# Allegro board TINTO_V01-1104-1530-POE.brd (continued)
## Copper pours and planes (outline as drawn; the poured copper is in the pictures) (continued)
GEN_3V3 on BOTTOM (solid shape): 139.4,153.53 139.4,152.48 140.57,151.32 140.57,149.41 140.32,149.16 139,149.16 138.84,149.31 138.84,150.66 138.01,151.49 134.91,151.49 134.86,151.54 134.86,153.51 134.96,153.61 139.32,153.61
GEN_3V3 on BOTTOM (solid shape): 136.18,167.14 136.18,164.35 136,164.17 132.75,164.17 132.74,164.17 132.6,164.19 132.45,164.17 132.44,164.17 131.96,164.17 131.66,164.47 131.66,167.05 131.91,167.31 132.76,167.31 132.77,167.32 136,167.32
GEN_3V3 on BOTTOM (solid shape): 144.38,82.79 144.38,77.71 141.21,74.53 134.6,74.53 134.22,74.15 134.22,50.28 131.43,47.48 108.7,47.48 107.16,45.94 107.16,31.46 106.91,31.22 106.09,31.22 105.88,31.42 105.88,47.21 107.93,49.26 130.79,49.26 132.44,50.91 132.44,75.04 133.21,75.8 140.95,75.8 142.99,77.83 142.99,80.63 142.81,80.8 141.92,80.8 141.92,80.81 138.24,80.81 137.37,79.94 137.37,78.67 137.3,78.6 136.69,78.6 136.64,78.65 136.64,80.12 135.95,80.81 131.84,80.81 131.76,80.88 131.76,83.22 131.99,83.45 143.72,83.45
GEN_3V3 on BOTTOM (solid shape): 102.86,145.02 102.86,144.79 102.53,144.46 102.53,144.05 102.63,143.79 102.88,143.69 102.91,143.69 102.96,143.65 102.96,143.44 102.85,143.34 102.7,143.34 102.55,143.19 102.55,142.99 102.45,142.88 102.38,142.89 102.27,142.88 102.22,142.94 102.22,143.16 102.45,143.56 102.2,143.94 102.16,143.95 102.16,144.02 102.11,144.21 101.95,144.32 101.89,144.33 101.82,144.32 101.71,144.34 101.66,144.44 101.66,144.64 101.7,144.68 102.14,144.68 102.16,144.69 102.61,145.14 102.73,145.14
GEN_3V3 on BOTTOM (solid shape): outline of 125 points within 100.26,147.39 102.21,149.95
GEN_3V3 on VCC1 (solid shape): outline of 233 points within 10.51,29.7 172.96,192.29
GEN_3V3_IN on BOTTOM (solid shape): 126.12,160.82 126.12,160.55 125.96,160.39 125.96,159.92 125.96,159.88 125.97,159.84 125.97,159.57 126.2,159.34 126.72,159.34 126.81,159.3 126.85,159.21 127.19,158.73 127.72,158.98 127.81,159.05 127.92,159.01 127.95,158.99 127.95,158.22 127.74,158.02 127.16,158.02 126.75,158.43 125.51,158.43 125.13,158.81 125.13,160.21 125.84,160.92 126.02,160.92
GEN_3V3_PMIC on BOTTOM (solid shape): 130.77,166 130.77,164.37 130.59,164.19 130.02,164.19 129.95,164.12 129.78,164.12 129.55,163.89 129.55,163.36 129.22,163.03 125.43,163.03 125.28,163.18 125.28,165.41 125.43,165.57 128.94,165.57 129.35,165.97 129.37,165.97 129.53,165.99 129.67,166.06 129.68,166.07 129.78,166.07 130.69,166.07
GEN_3V3_SW on BOTTOM (solid shape): 127.57,162.44 127.57,162.3 127.56,162.29 127.56,161.82 127.28,161.54 126.68,161.54 126.38,161.25 125.89,161.25 125.76,161.12 125.76,161.12 125.7,161.07 125.69,161.06 125.59,160.99 125.51,160.88 125.51,160.88 124.92,160.29 124.92,159.49 124.87,159.44 124.72,159.44 124.62,159.55 124.62,160.89 125.23,161.5 125.23,162.31 125.43,162.52 127.49,162.52
GLH on TOP (solid shape): 77.33,106.54 87.23,106.54 88.63,107.93 90.15,107.93 92.36,105.73 92.36,102.61 92.1,102.35 89.52,102.35 87.36,104.5 76.95,104.5 76.18,105.27 72.37,105.27 71.99,105.65 71.99,107.81 72.5,108.31 75.55,108.31
GLH on BOTTOM (solid shape): 77.33,106.54 87.23,106.54 88.63,107.93 90.15,107.93 92.36,105.73 92.36,102.61 92.1,102.35 89.52,102.35 87.36,104.5 76.95,104.5 76.18,105.27 72.37,105.27 71.99,105.65 71.99,107.81 72.5,108.31 75.55,108.31
LAN_AVDDL on BOTTOM (solid shape): 108.57,120.51 108.57,120.32 108.31,120.06 107.52,120.06 107.4,119.94 107.2,119.94 107.01,120.12 107.01,120.35 107.3,120.63 108.44,120.63
LAN_DVDD_SW on BOTTOM (solid shape): 105.44,116.56 105.64,116.56 105.82,116.41 105.97,116.36 106.02,116.36 106.08,116.36 106.49,116.36 106.49,116.36 106.54,116.32 106.54,113.9 106.41,113.78 105.39,113.78 105.22,113.95 105.22,115.78 104.89,116.11 104.89,116.78 104.89,116.87 104.91,116.9 105.1,116.9
LCD_AVDD on BOTTOM (solid shape): 125.61,76.72 125.61,75.19 124.98,74.56 122.69,74.56 122.44,74.81 122.44,75.06 122.82,75.45 122.82,77.1 125.23,77.1
LCD_BL+ on BOTTOM (solid shape): 119.24,67.17 119.24,65.39 118.47,64.63 117.05,64.63 116.34,63.92 115.99,63.92 115.91,63.99 115.91,64.98 115.88,65.01 115.73,65.01 115.71,64.98 115.71,63.97 115.66,63.92 115.45,63.92 115.4,63.97 115.4,65.13 115.17,65.36 115.17,67.17 115.3,67.29 119.11,67.29
LCD_BL- on BOTTOM (solid shape): 112.2,64.93 112.2,63.31 112.07,63.18 111.46,63.18 111.39,63.26 111.39,64.93 111.46,65.01 112.12,65.01
LCD_SUP on BOTTOM (solid shape): 122.34,80.24 122.34,75.89 122.03,75.58 119.63,75.58 119.39,75.81 119.39,77.64 119.24,77.79 117.86,77.79 117.61,78.05 117.61,80.53 117.43,80.7 115.96,80.7 115.95,80.7 115.8,80.73 115.65,80.7 115.64,80.7 115.55,80.7 114.78,79.93 113.72,79.93 113.62,80.03 113.62,80.31 113.74,80.42 114.6,80.42 114.71,80.53 114.71,80.53 114.79,80.59 114.85,80.67 114.85,80.67 115.56,81.38 121.19,81.38
LCD_VDD on BOTTOM (solid shape): 96.41,66.74 97.37,66.74 97.73,66.38 97.73,66.25 97.72,66.24 97.65,66.01 97.73,65.79 97.73,63.94 97.64,63.85 96.97,63.85 96.87,63.95 96.87,64.31 96.88,64.32 96.91,64.46 96.88,64.6 96.87,64.61 96.87,65.18 96.14,65.91 92.66,65.91 92.52,66.05 92.52,67.06 92.59,67.13 96.02,67.13
LED_G_POWER_L on BOTTOM (solid shape): 51.19,184.1 51.19,176.04 51.04,175.88 46.97,175.88 46.65,176.21 46.65,182.41 47.49,183.24 47.49,183.97 47.84,184.33 50.97,184.33
LED_R_POWER_L on BOTTOM (solid shape): 68.44,184.01 68.44,182.61 69.25,181.79 69.25,175.94 69.2,175.89 65.02,175.89 64.98,175.93 64.98,179.82 64.75,180.04 64.75,182.36 65.45,183.05 65.45,183.94 65.64,184.13 68.31,184.13
LVDS_2V5 on VCC2 (solid shape): 140.06,155.45 140.06,151.49 140.08,151.4 140.14,151.31 140.95,150.5 140.95,147.41 133.15,139.61 133.1,139.53 133.08,139.43 133.1,139.34 133.14,139.26 133.14,137.98 132.44,137.28 132.4,137.22 132.38,137.14 132.38,135.57 132.24,135.43 130.35,135.43 130.35,141.64 130.67,141.96 130.68,141.97 131.3,141.97 131.4,141.99 131.48,142.04 131.86,142.42 131.92,142.51 131.94,142.6 131.94,146.94 135.8,150.81 135.85,150.89 135.87,150.99 135.87,157.7 136.02,157.84 137.67,157.84
NVCC_3V3 on BOTTOM (solid shape): 111.46,129.4 111.46,129.37 111.47,129.27 111.5,129.16 111.51,129.15 111.51,127.64 111.11,127.24 110.63,127.24 110.25,126.86 109.71,126.86 109.46,127.11 109.46,127.49 109.63,127.66 109.75,127.66 109.86,127.77 109.93,127.82 109.99,127.89 110.22,128.13 110.22,128.63 111.01,129.42 111.06,129.47 111.1,129.52 111.34,129.52
NVCC_3V3 on VCC1 (solid shape): 123.49,130.84 123.49,129.86 123.35,129.71 122.21,129.71 121.44,128.95 120.3,128.95 119.54,128.19 119.53,128.19 119.47,128.25 112.86,128.25 112.1,129.02 111.09,129.02 110.85,129.25 110.85,130.18 111.09,130.41 116.8,130.41 116.86,130.48 121.98,130.48 122.49,130.98 123.35,130.98
NVCC_EIM on VCC1 (solid shape): 127.17,126.78 127.17,126.14 127.81,125.51 127.81,120.84 127.41,120.44 125.03,120.44 124.76,120.71 124.76,126.52 125.41,127.17 126.78,127.17
NVCC_PLL_LDO on BOTTOM (solid shape): 116,146.27 116,145.86 116.56,145.31 116.56,144.71 116.38,144.54 114.51,144.54 114.34,144.71 114.34,146.44 114.45,146.55 115.73,146.55
NVCC_RGMII on BOTTOM (solid shape): 108.14,131.5 108.14,131.07 108.28,130.93 108.28,130.01 109.13,129.17 109.13,128.13 108.95,127.95 108.8,127.95 108.7,127.99 108.67,128.09 108.51,128.48 108.09,128.57 108.05,128.56 108.03,128.58 107.7,128.58 107.69,128.59 107.56,128.6 107.43,128.59 107.42,128.58 107.22,128.58 107.21,128.59 107.21,129.06 107.16,129.12 107.16,129.9 107.21,130.19 107.07,130.44 107.07,131.37 107.27,131.57 108.06,131.57
NVCC_SD1 on VCC2 (solid shape): 116.77,132.52 116.85,132.46 116.95,132.44 117.04,132.46 117.12,132.51 123.35,132.51 123.49,132.37 123.49,130.67 123.51,130.59 123.55,130.53 123.75,130.33 123.75,128.84 123.35,128.44 113.73,128.44 113.28,128.89 113.22,128.94 113.14,128.95 111.82,128.95 111.55,129.22 111.55,129.83 112.52,130.79 112.69,130.87 112.76,131.05 112.76,133.83 112.77,133.83 113.03,134.1 115.19,134.1
NVCC_SD2 on VCC1 (solid shape): 123.75,129.19 123.75,129.09 123.36,128.71 123.36,128.33 122.84,127.81 122.08,127.81 121.21,126.94 121.21,126.9 121.14,126.83 121.14,123.44 120.94,123.24 110.3,123.24 109.39,124.14 109.39,125 110.3,125.9 111.41,125.9 111.55,125.76 111.55,125.25 111.92,124.89 116.78,124.89 117.9,126.02 117.9,127.54 118.11,127.75 119.47,127.75 119.53,127.81 119.7,127.81 120.46,128.57 121.6,128.57 122.36,129.33 123.6,129.33
PA_3V3 on BOTTOM (solid shape): 27.2,51.87 27.2,50.95 26.99,50.73 24.57,50.73 24.38,50.55 24.38,50.55 24.38,49.78 24.33,49.72 23.5,49.72 23.42,49.8 23.42,50.13 23.18,50.37 22.62,50.37 22.57,50.42 22.57,51.03 23.27,51.74 25.67,51.74 25.84,51.92 27.16,51.92
PMIC_VSNVS on BOTTOM (solid shape): 128.51,152.13 128.51,151.78 128.52,151.77 128.52,151.75 128.87,151.4 128.87,151.35 128.71,151.19 128.35,151.19 128.26,151.22 128.22,151.31 128.09,151.61 127.79,151.74 127.7,151.78 127.67,151.87 127.67,152.02 127.66,152.11 127.62,152.2 127.62,152.21 127.62,152.28 127.72,152.38 128.25,152.38
PMU3V on BOTTOM (solid shape): 140.97,164.43 140.97,161.91 140.98,161.83 140.99,161.76 140.99,161.72 140.69,161.42 138.9,161.42 138.54,161.78 138.54,163.94 139.38,164.78 140.62,164.78
PMU3V on VCC1 (solid shape): 131.71,163.69 136.23,163.69 137.63,165.08 140.21,165.08 140.7,164.6 140.7,160.36 132.98,152.64 121.25,152.64 118.73,155.16 118.73,161.51 115.4,164.83 97.37,164.83 96.12,166.08 96.12,173.49 96.86,174.23 121.16,174.23
POE_PRI_SW_NODE on TOP (solid shape): 58.15,154.16 58.15,147.43 57.39,146.67 53.83,146.67 53.2,147.3 53.2,152.51 54.97,154.29 58.02,154.29
POE_PRI_SW_NODE on BOTTOM (solid shape): 58.66,150.73 58.66,143.75 58.4,143.49 57.51,143.49 57.26,143.75 57.26,145.65 56.24,146.67 53.7,146.67 53.2,147.18 53.2,150.99 53.45,151.24 58.15,151.24
POE_RTN on TOP (solid shape): 52.18,145.65 52.18,142.73 51.8,142.35 47.35,142.35 46.85,142.86 46.85,145.78 47.35,146.29 51.55,146.29
POE_RTN on TOP (solid shape): 71.99,153.78 71.99,148.95 71.48,148.45 68.06,148.45 67.67,148.83 67.67,153.91 68.06,154.29 71.48,154.29
POE_RTN on TOP (solid shape): 76.69,143.49 76.69,137.65 76.06,137.02 72.88,137.02 72.5,137.4 72.5,143.62 72.88,144 76.18,144
POE_RTN on BOTTOM (solid shape): 63.61,146.54 63.61,143.75 63.36,143.49 62.59,143.49 62.21,143.87 62.21,146.54 62.34,146.67 63.48,146.67
POE_RTN on BOTTOM (solid shape): 71.74,154.03 71.74,152.38 71.48,152.13 63.48,152.13 63.23,152.38 63.23,153.91 63.61,154.29 71.48,154.29
POE_RTN on BOTTOM (solid shape): 73.9,133.84 73.9,132.7 73.64,132.44 69.71,132.44 69.33,132.83 69.33,133.97 69.45,134.1 73.64,134.1
POE_RTN on BOTTOM (solid shape): 76.69,143.49 76.69,137.65 76.06,137.02 72.88,137.02 72.5,137.4 72.5,143.62 72.88,144 76.18,144
POE_RTN on GND2 (solid shape): 91.3,156.92 91.3,138.01 90.94,137.65 81.79,137.65 80.78,136.64 80.78,136.64 80.63,136.49 80.63,131.92 80.14,131.43 72.16,131.43 71.27,132.32 68.67,132.32 68.06,132.93 68.06,142.46 67.02,143.49 52.96,143.49 51.7,142.22 46.89,142.22 46.47,142.65 46.47,146.5 56.92,156.96 79.91,156.96 80.67,157.72 90.49,157.72
POE_VDD on TOP (solid shape): 85.07,144.38 85.07,141.84 84.95,141.72 84.44,141.72 84.31,141.59 84.31,140.57 84.57,140.32 85.33,140.32 85.58,140.06 85.58,138.67 85.07,138.16 78.98,138.16 77.96,139.18 77.96,143.62 78.85,144.51 84.95,144.51
POE_VDD on BOTTOM (solid shape): 82.41,152.76 82.41,147.81 84.31,145.91 84.31,138.79 83.8,138.29 82.41,138.29 80.63,136.51 80.63,132.06 80.12,131.56 76.18,131.56 75.68,132.06 75.68,133.97 77.45,135.75 77.45,152.64 77.96,153.15 82.03,153.15
POE_VDD_CN on BOTTOM (solid shape): 84.57,127.36 84.57,125.71 84.44,125.59 82.15,125.59 82.03,125.71 82.03,127.36 82.15,127.49 84.44,127.49
POE_VDD_CN on BOTTOM (solid shape): 77.58,130.29 77.58,129.02 76.31,127.75 76.31,126.09 75.93,125.71 74.28,125.71 74.02,125.97 74.02,130.16 74.28,130.41 77.45,130.41
POE_VDD_CN on IN2 (solid shape): 84.57,127.87 84.57,125.84 84.31,125.59 74.28,125.59 74.02,125.84 74.02,128 74.28,128.25 84.18,128.25
POE_VSS on TOP (solid shape): 85.07,150.35 85.07,148.7 83.93,148.7 83.8,148.83 83.8,150.35 83.93,150.48 84.95,150.48
POE_VSS on BOTTOM (solid shape): 86.6,136.25 86.6,131.68 86.34,131.43 81.77,131.43 81.52,131.68 81.52,136.51 81.9,136.89 85.96,136.89
POE_VSS on GND1 (solid shape): 84.95,150.37 84.95,146.95 85.09,146.8 85.1,146.8 86.98,144.91 86.98,128.49 86.49,128 81.94,128 81.39,128.55 81.39,150.12 81.88,150.61 84.71,150.61
POE_VSS_CN on BOTTOM (solid shape): 87.49,130.16 87.49,125.84 87.3,125.65 85.65,125.65 85.45,125.84 85.45,127.11 84.82,127.75 81.14,127.75 79.1,125.71 77.33,125.71 77.2,125.84 77.2,127.36 80.25,130.41 87.23,130.41
SATA_VP on VCC1 (solid shape): 123.49,132.24 123.49,131.51 123.35,131.37 122.33,131.37 121.83,130.86 117.41,130.86 117.14,131.13 117.14,132.11 117.28,132.25 121.6,132.25 121.86,132.51 123.22,132.51
SATA_VPH on VCC1 (solid shape): 123.62,133.76 123.62,133.16 123.35,132.89 121.7,132.89 121.44,132.64 117.28,132.64 117.14,132.78 117.14,134.14 117.28,134.29 123.1,134.29
SENSOR_3V3 on BOTTOM (solid shape): 106.26,183.59 106.26,182.92 106.18,182.84 105.71,182.84 105.58,182.72 105.54,182.72 105.54,182 105.54,182 105.54,180.56 105.2,180.22 105.11,180.22 105.09,180.24 104.76,180.37 104.44,180.22 102.37,180.22 102.24,180.35 102.24,183.4 102.5,183.65 106.2,183.65
SENSOR_5V on BOTTOM (solid shape): 101.86,183.4 101.86,180.35 101.67,180.16 99.43,180.16 99.32,180.17 99.21,180.16 98.8,180.16 98.69,180.17 98.58,180.16 96.97,180.16 96.78,180.35 96.78,183.14 97.29,183.65 101.61,183.65
SW1CLX on BOTTOM (solid shape): 117.81,161.15 117.81,159.23 119.08,157.96 119.17,157.96 119.19,157.95 119.41,157.89 119.64,157.95 119.66,157.96 119.86,157.96 119.96,157.86 120.59,157.86 120.69,157.88 120.79,157.93 120.83,157.93 120.86,157.94 120.94,157.86 120.94,157.62 120.88,157.57 120.67,157.57 120.63,157.57 120.59,157.58 119.8,157.58 119.79,157.57 117.82,157.57 116.46,158.93 116.46,161.02 116.72,161.27 117.68,161.27
SW1LX on BOTTOM (solid shape): 118.02,156.65 118.98,156.65 118.99,156.65 119.13,156.62 119.28,156.65 119.31,156.65 119.38,156.7 119.42,156.73 119.96,156.73 120.04,156.8 120.2,156.8 120.26,156.86 120.59,156.86 120.67,156.87 120.74,156.9 120.75,156.9 120.94,156.9 121.06,156.78 121.06,156.17 120.94,156.04 120.74,156.04 120.66,156.07 120.59,156.08 120.04,156.08 120.03,156.08 119.67,156.08 119.42,155.83 119.4,155.79 118.82,155.79 118.41,155.38 117.32,155.38 116.74,154.79 115.63,154.79 115.45,154.97 115.45,157.39 115.7,157.64 117.03,157.64
SW3LX on BOTTOM (solid shape): 134.37,157.53 134.37,155.07 134.12,154.82 133.05,154.82 132.16,155.71 130.64,155.71 130.56,155.63 130.35,155.63 130.33,155.64 130.05,155.71 129.77,155.63 128.18,155.63 128.1,155.72 128.1,156.26 128.2,156.36 129.29,156.36 129.83,156.9 130.29,156.9 130.76,157.38 131.88,157.38 132.15,157.65 134.25,157.65
SW4LX on BOTTOM (solid shape): 124.7,166.06 124.7,161.26 124.42,160.98 124.42,159.52 124.34,159.44 124.24,159.44 124.09,159.6 124.09,159.73 124.1,159.74 124.13,159.83 124.14,159.92 124.14,160.65 124.14,160.66 124.14,160.9 123.68,161.36 123.68,161.83 122.82,162.69 122.82,162.7 121.78,163.73 121.78,166.12 121.9,166.24 124.51,166.24
SW_T on BOTTOM (solid shape): 121.17,85.35 121.17,82.34 120.78,81.96 113.67,81.96 113.59,82.03 113.59,82.75 113.67,82.83 113.84,82.83 113.84,82.84 115.19,82.84 115.32,82.96 115.35,82.96 116.59,84.21 116.59,85.61 117.07,86.09 118.15,86.09 118.17,86.11 120.4,86.11
SYS_5V on BOTTOM (solid shape): 37.48,103.72 37.48,92.34 36.64,91.5 33.61,91.5 31.86,93.25 31.86,103.33 32.56,104.03 37.17,104.03
VGEN4_1V8 on BOTTOM (solid shape): 134.27,162.09 134.27,160.92 134.2,160.84 132.85,160.84 132.67,161.02 132.37,161.02 132.19,161.2 131.13,161.2 131.05,161.28 131.05,162.11 131.15,162.21 134.15,162.21
VSNVS_3V0 on VCC2 (solid shape): 129.9,167.87 129.9,167.86 129.9,164.3 125.79,160.18 125.73,160.1 125.71,160 125.71,159.11 125.73,159.02 125.79,158.93 126.6,158.12 126.6,153.63 126.24,153.27 125.21,153.27 125.11,153.25 125.03,153.2 124.64,152.82 124.59,152.74 124.57,152.64 124.57,151.98 123.76,151.17 123.7,151.08 123.68,150.99 123.68,146.92 123.7,146.83 123.76,146.74 124.14,146.36 124.22,146.31 124.32,146.29 126.75,146.29 126.98,146.05 126.98,144.76 127,144.67 127.06,144.58 129.6,142.04 129.67,141.99 129.76,141.97 129.97,141.76 129.97,135.44 129.83,135.3 124.06,135.3 123.99,135.29 123.92,135.24 123.55,134.87 123.51,134.81 123.49,134.73 123.49,133.03 123.35,132.89 117.12,132.89 115.48,134.53 115.4,134.59 115.3,134.6 113.16,134.6 113.15,134.61 112.77,134.99 112.76,135 112.76,164.19 112.74,164.29 112.69,164.38 112.18,164.88 112.1,164.94 112,164.96 106.66,164.96 106.57,164.94 106.48,164.88 104.45,162.85 104.4,162.77 104.38,162.67 104.38,137.92 104.37,137.91 104.11,137.65 103.21,137.65 103.11,137.76 103.11,138.92 103.09,139.02 103.03,139.1 99.55,142.58 99.55,162.18 105.5,168.13 129.64,168.13
WLAN_3VIN on BOTTOM (solid shape): 28.62,50.71 28.62,47.08 28.27,46.73 22.7,46.73 22.35,47.08 22.35,48.37 22.6,48.61 22.6,49.35 22.65,49.39 23.71,49.39 24.34,48.77 24.34,47.65 27.24,47.65 27.59,48 27.59,50.74 27.7,50.85 28.48,50.85
N2030210 on BOTTOM (solid shape): 131.45,160.26 131.45,159.77 131.43,159.75 131.34,159.75 131.22,159.62 129.88,159.62 129.6,159.34 129.07,159.34 128.99,159.26 128.94,159.24 128.88,159.19 128.84,159.19 128.71,159.06 128.25,159.06 128.13,159.18 128.13,159.34 128.28,159.5 128.47,159.5 129.33,160.36 131.35,160.36
N17701522 on BOTTOM (solid shape): 40.09,175.44 40.09,174.87 40.23,174.72 40.26,174.71 40.29,174.69 40.51,174.47 40.88,174.47 41.36,173.99 41.45,173.9 47.09,173.9 47.8,174.61 50.91,174.61 51.4,174.12 51.4,170.27 51.04,169.91 46.66,169.91 46.28,170.29 46.28,170.31 43.55,173.03 41.29,173.03 39.83,174.5 39.83,175.46 39.9,175.54 39.99,175.54
N17701606 on BOTTOM (solid shape): 41.39,170.42 41.39,168.39 41.13,168.13 38.46,168.13 38.34,168.26 38.34,169.8 38.67,170.14 39.54,170.14 39.79,170.39 39.79,170.8 41,170.8
N17702263 on BOTTOM (solid shape): 39.56,175.44 39.56,174.18 40.02,173.72 40.02,171.34 39.52,170.84 39.52,170.58 39.34,170.4 38.56,170.4 38.37,170.6 38.37,173.76 39.31,174.7 39.31,174.99 39.34,175.02 39.34,175.23 39.34,175.31 39.31,175.39 39.31,175.48 39.52,175.48
N17702392 on BOTTOM (solid shape): 51.31,168.37 51.31,167.14 51.32,167.12 51.32,160.03 50.78,159.5 46.68,159.5 46.68,162.2 42.84,166.05 42.84,167.43 43.29,167.88 44.37,167.88 45.58,169.08 50.59,169.08
N18409851 on BOTTOM (solid shape): 69.03,168.31 69.03,159.83 68.69,159.5 64.8,159.5 64.63,159.67 64.63,162.1 60.69,166.04 60.69,167.37 61.2,167.88 61.83,167.88 63.1,169.15 68.18,169.15
N18409953 on BOTTOM (solid shape): 58.15,175.42 58.15,174.85 58.47,174.52 60.43,174.52 61.02,173.93 64.41,173.93 65.39,174.9 68.71,174.9 69.38,174.23 69.38,170.6 68.69,169.91 64.76,169.91 61.9,172.77 61.19,172.77 60.05,173.9 58.45,173.9 57.85,174.5 57.85,175.48 57.93,175.56 58.01,175.56
N18409965 on BOTTOM (solid shape): 59.42,170.54 59.42,168.13 56.63,168.13 56.24,168.51 56.24,170.29 56.75,170.8 59.17,170.8
N18410031 on BOTTOM (solid shape): 57.63,175.58 57.63,174.24 58.04,173.83 58.04,171.33 57.77,171.05 56.75,171.05 56.48,171.33 56.48,173.86 57.34,174.73 57.34,175.56 57.39,175.61 57.6,175.61
N19092772 on BOTTOM (solid shape): 126.42,152.31 126.42,151.72 126.5,151.64 126.5,150.79 126.42,150.71 126.42,147.1 126.08,146.76 124.29,146.76 124.17,146.87 124.17,148.58 124.29,148.88 124.17,149.18 124.17,150.36 124.28,150.46 124.28,150.74 124.34,150.81 124.4,150.82 124.45,150.84 125.06,150.84 125.18,150.82 125.29,150.84 125.63,150.84 125.64,150.83 125.95,150.82 126.2,151.01 126.27,151.3 126.15,151.57 126.15,151.83 126.12,151.86 126.12,152.02 126.12,152.06 126.09,152.15 126.09,152.28 126.22,152.41 126.32,152.41
N19097147 on BOTTOM (solid shape): 126.96,152.33 126.96,152.21 126.96,152.21 126.98,152.18 126.98,152.15 126.96,152.09 126.96,152.02 126.96,151.56 127.31,151.21 127.31,151.19 127.44,150.96 127.68,150.83 127.76,150.82 127.84,150.83 127.91,150.85 127.98,150.88 128.04,150.92 128.09,150.96 128.29,150.96 128.86,150.39 128.86,150.1 129.45,149.51 129.45,147.99 128.58,147.12 128.58,146.93 128.38,146.73 126.81,146.73 126.63,146.92 126.63,150.62 126.71,150.7 126.71,151.73 126.63,151.81 126.63,152.33 126.68,152.38 126.91,152.38
N24701014 on BOTTOM (solid shape): 167.08,66.97 167.08,65.58 166.82,65.32 166.44,65.32 166.23,65.53 166.23,66.24 166.12,66.34 166.12,66.99 166.12,66.99 166.12,67.44 166.18,67.49 166.56,67.49
N24744807 on BOTTOM (solid shape): 171.65,67.18 171.65,65.7 171.42,65.47 171.02,65.47 170.81,65.68 170.81,66.34 170.7,66.45 170.7,67.12 170.7,67.12 170.7,67.55 170.77,67.62 171.22,67.62
N25585918 on BOTTOM (solid shape): 62.85,153.02 62.85,152 62.47,151.62 56.5,151.62 56.37,151.75 56.37,153.27 62.59,153.27
N25586657 on BOTTOM (solid shape): 76.43,156.58 76.43,145.43 76.24,145.24 70.79,145.24 68.75,147.29 62.07,147.29 61.3,146.52 61.3,143.79 61.03,143.51 59.64,143.51 59.37,143.78 59.37,151.02 59.58,151.23 62.79,151.23 63.77,150.25 71.61,150.25 72.75,151.39 72.75,156.57 72.88,156.7 76.31,156.7
N25586882 on BOTTOM (solid shape): 68.63,129.71 68.63,122.86 68.44,122.67 66.4,122.67 65.9,123.17 62.34,123.17 61.83,123.68 61.83,126.73 62.28,127.17 62.28,129.71 62.72,130.16 68.18,130.16
N25586910 on TOP (solid shape): 65.01,152.26 65.01,149.08 64.63,148.7 61.07,148.7 60.31,149.46 60.31,152.64 60.69,153.02 64.25,153.02
N25587015 on BOTTOM (solid shape): 61.2,129.65 61.2,126.98 59.42,125.21 59.42,119.87 59.04,119.49 55.99,119.49 55.61,119.87 55.61,126.86 56.75,128 56.75,129.9 57.13,130.29 60.56,130.29
N25600625 on BOTTOM (solid shape): 61.71,110.35 61.71,103.74 60.69,102.73 56.75,102.73 55.99,103.49 55.99,110.22 56.37,110.6 61.45,110.6
N25600639 on BOTTOM (solid shape): 60.31,114.54 60.31,111.36 60.05,111.11 57.13,111.11 56.88,111.36 56.88,114.66 57.01,114.79 60.05,114.79
N25600655 on BOTTOM (solid shape): 58.28,118.35 58.28,115.93 58.02,115.68 56.12,115.68 55.74,115.3 55.74,111.49 54.92,110.68 53.24,110.68 53.23,110.66 51.99,110.66 51.55,110.22 51.55,107.93 51.16,107.55 47.99,107.55 47.48,108.06 47.48,118.09 48.37,118.98 57.64,118.98
N25600703 on BOTTOM (solid shape): 64.25,112.76 64.25,108.7 63.99,108.44 62.59,108.44 62.34,108.7 62.34,110.35 61.07,111.62 61.07,113.14 61.2,113.27 63.74,113.27
N25856521 on BOTTOM (solid shape): 53.45,122.03 53.45,119.62 53.32,119.49 50.15,119.49 49.89,119.74 49.89,121.9 50.15,122.16 53.32,122.16
N27686456 on BOTTOM (solid shape): 40.41,51.01 41.23,51.01 41.82,50.43 41.82,49.97 42.05,49.74 42.05,47.23 41.94,47.13 41.21,47.13 40.9,47.43 40.9,49.44 39.2,51.14 38.44,51.14 38.34,51.24 38.34,51.75 38.41,51.83 39.6,51.83
N27686764 on BOTTOM (solid shape): 40.37,49.51 40.37,47.23 40.24,47.1 39.4,47.1 39.23,47.28 39.23,49.26 38.83,49.66 37.08,49.66 36.94,49.8 36.94,50.66 37.07,50.78 39.1,50.78

Small or netless copper shapes (teardrops, artwork), in the pictures only: 6 on BOTTOM

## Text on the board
BOTTOM: 8
GND1: 2
VCC1: VCC1(L4) | 4
VCC2: VCC2(L5) | 5
GND2: 7
DIMENSION: PASTEMASK_TOP
DISPLAY_BOTTOM: PASTEMASK_BOT
User.11: VDD_ARM_CAP | NVCC_SD1 | VSNVS_3V0 | LVDS_2V5 | GEN_1V8 | ETH_3V3 | VDDSOC | DDR_VREF | 5VDDM | GND | VDDSOC_CAP
User.12: VDD13_12 | SATA_VPH | SATA_VP | NVCC_SD2 | GEN_3V3 | GND | VDDCORE | NVCC_3V3 | PMU3V | VDDPU | DDR_1V5 | ETH_3V3 | NVCC_EIM
User.13: GND | POE_VSS
User.14: POE_RTN | GND
User.32: FIGURE | SIZE | 10.0 | 31.5 | 35.43 | 39.37 | 40.0 | 51.18 | 59.06 | 129.92 | 145.67 | 224.41 | 255.91 | 62.99 | 127.95 | 160.0 | 39.37x62.99 | 31.5x78.74 | 118.11x31.5 | DRILL CHART: TOP to BOTTOM | ALL UNITS ARE IN MILS | PLATED | NON-PLATED | QTY | 3357 | 4 | 10 | 8 | 9 | 2 | 1 | 6 | 7
User.45: XY-Create nettxt:Oct 05 18:27:32 2015 | XY-Create plane:Oct 05 18:29:08 2015 | create nettxt:Oct 05 18:27:32 2015 | create plane:Oct 05 18:29:08 2015 | Excess check:Oct 28 17:58:09 2015 | GNDVIA_CHECK:Oct 28 17:43:17 2015 | PadStack_Check:Oct 28 13:05:25 2015 | XY-Check acute:Oct 28 14:47:23 2015 | XY-Check cline width:Oct 28 18:02:12 2015 | XY-Check rotation:Oct 28 18:05:33 2015 | XY-Check txt overlap:Oct 28 18:30:26 2015 | XY-Check txt:Oct 28 18:34:52 2015 | XY-Create nettxt:Oct 19 13:55:21 2015 | XY-Create plane:Oct 29 08:38:25 2015 | XY-Dxf to pin check:Oct 28 14:38:41 2015 | XY-Excess check:Oct 28 17:58:09 2015 | XY-GNDVIA_CHECK:Oct 28 17:43:17 2015 | XY-Mask check:Oct 29 11:16:50 2015 | XY-PadStack_Check:Oct 28 13:05:25 2015 | XY-Plane net check:Oct 29 08:39:59 2015 | XY-bbvia check:Oct 28 17:18:51 2015 | XY-shape min check:Oct 28 18:53:26 2015 | XY-shape pin check:Oct 28 17:48:13 2015 | XY-via check:Oct 28 14:59:37 2015 | bbvia check:Oct 28 17:18:51 2015 | check acute:Oct 28 14:47:23 2015 | check cline width:Oct 28 18:02:12 2015 | check rotation:Oct 28 18:05:33 2015 | check txt overlap:Oct 28 18:30:26 2015 | check txt:Oct 28 18:34:52 2015 | create nettxt:Oct 19 13:55:21 2015 | create plane:Oct 29 08:38:25 2015 | dxf to pin check:Oct 28 14:38:41 2015 | plane net check:Oct 29 08:39:59 2015 | shape min check:Oct 28 18:53:26 2015 | shape pin check:Oct 28 17:48:13 2015 | via check:Oct 28 14:59:37 2015
